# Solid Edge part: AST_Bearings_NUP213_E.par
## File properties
Author: Nimesh.N
Template: iso metric part.par
Last saved by: Nimesh.N
Revision: 35
Application: Solid Edge
Density: 7800.000 kg/m^3
Accuracy: 0.990
Username: Nimesh.N
Material: Steel - Alloyed:1.7016 , 17Cr3
Face Style: Steel
Fill Style: ANSI32(Steel)
Virtual Style: ANSI32(Steel)
Grouping: Steel\Steel - Alloyed (Cr)
LibraryName: Materials-DIN
Coef. of Thermal Exp: 1.1e-05
Thermal Conductivity: 14.0
Specific Heat: 440.0
Modulus of Elasticity: 210000003072.0
Poisson's Ratio: 0.28
Yield Stress: 420000000.0
Ultimate Stress: 550000000.0
Elongation: 0.0
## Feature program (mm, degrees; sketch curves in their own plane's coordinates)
body "unnamed Body 1"
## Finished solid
Body 1: solid body, 182 faces, 632 edges, 358 vertices.
  Faces by surface: plane 120, cylinder 54, torus 8
  Edges by curve: circle 542, line 90
Bounding box of the edges (mm; curved faces can reach further): 23.000 x 120.000 x 120.000, from (-11.5, -60, -60) to (11.5, 60, 60).
Cylindrical faces by radius (mm): R6.875 x32, R32.5 x4, R39.375 x2, R41.4375 x4, R45.2188 x2, R47.2812 x2, R51.0625 x4, R53.125 x2, R60 x2
Toroidal faces (ring radius, tube radius in mm): R33.65 r1.15 x4, R58.85 r1.15 x4
Planar faces by outward normal: +x 68, -x 52
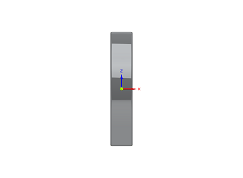
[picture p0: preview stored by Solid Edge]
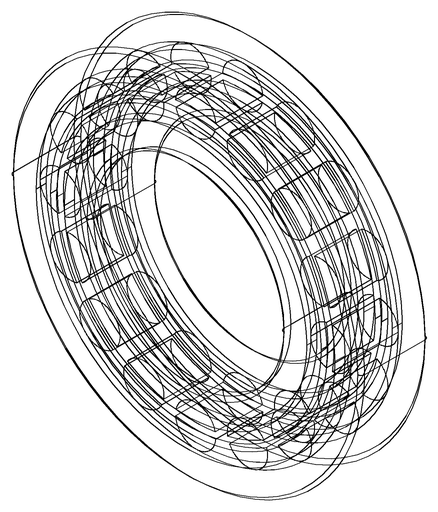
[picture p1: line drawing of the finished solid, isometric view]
